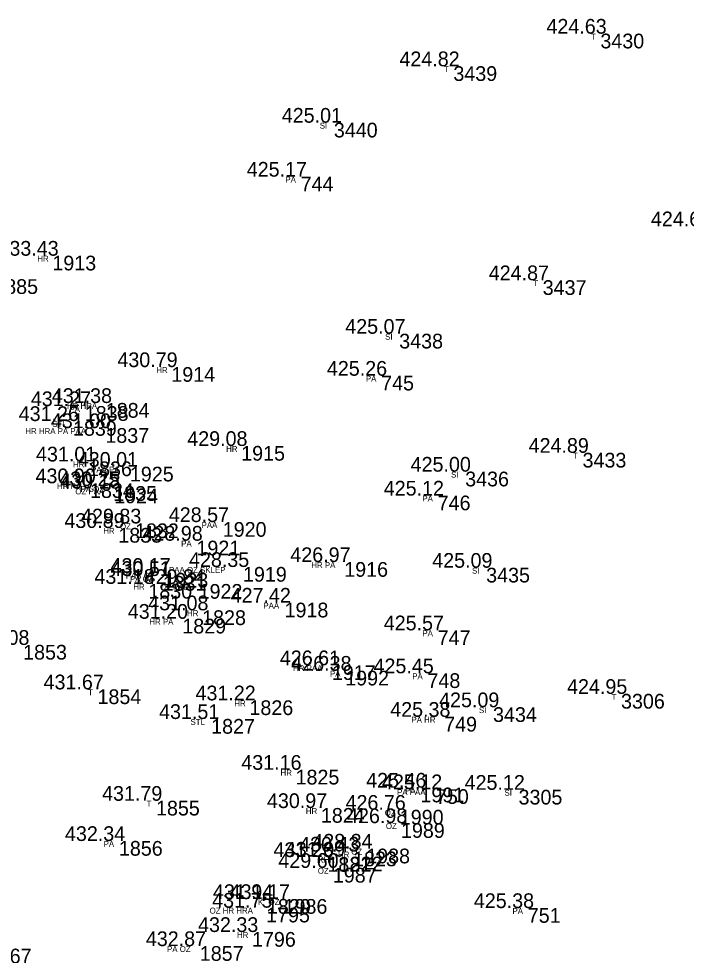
# Model space of a CAD drawing. Extents: x -639390 to -639075, y -1138747 to -1138358.
# Drawn here: x -639298.56 to -639264.56, y -1138517.05 to -1138469.3 of the extents above; entities that cross this region are included whole.
import ezdxf

# ---------------------------------------------------------------- set-up
doc = ezdxf.new("R2010")
doc.units = 0
for name, color, linetype in [('Vrstva 11', 7, 'Continuous'), ('Vrstva 12', 7, 'Continuous'), ('Vrstva 13', 7, 'Continuous'), ('Vrstva 57', 7, 'Continuous')]:
    doc.layers.add(name, color=color, linetype=linetype)

msp = doc.modelspace()

# ---------------------------------------------------------------- linework, layer by layer
at = {"layer": 'Vrstva 11'}
for p, q in [((-639269.21, -1138470.06), (-639269.21, -1138470.06)), ((-639276.7, -1138471.72), (-639276.7, -1138471.72)), ((-639282.79, -1138474.6), (-639282.79, -1138474.6)), ((-639284.48, -1138477.35), (-639284.48, -1138477.35)), ((-639297.13, -1138481.38), (-639297.13, -1138481.38)), ((-639272.15, -1138482.63), (-639272.15, -1138482.63)), ((-639279.46, -1138485.36), (-639279.46, -1138485.36)), ((-639291.07, -1138487.06), (-639291.07, -1138487.06)), ((-639280.38, -1138487.5), (-639280.38, -1138487.5)), ((-639294.41, -1138488.89), (-639294.41, -1138488.89)), ((-639295.48, -1138489.05), (-639295.48, -1138489.05)), ((-639296.08, -1138489.81), (-639296.08, -1138489.81)), ((-639294.43, -1138490.17), (-639294.43, -1138490.17)), ((-639287.51, -1138491.08), (-639287.51, -1138491.08)), ((-639270.12, -1138491.43), (-639270.12, -1138491.43)), ((-639295.31, -1138491.87), (-639295.31, -1138491.87)), ((-639293.18, -1138492.14), (-639293.18, -1138492.14)), ((-639276.1, -1138492.39), (-639276.1, -1138492.39)), ((-639295.21, -1138492.98), (-639295.21, -1138492.98)), ((-639294.03, -1138493.13), (-639294.03, -1138493.13)), ((-639293.98, -1138493.25), (-639293.98, -1138493.25)), ((-639277.5, -1138493.61), (-639277.5, -1138493.61)), ((-639292.92, -1138495.03), (-639292.92, -1138495.03)), ((-639288.45, -1138494.96), (-639288.45, -1138494.96)), ((-639293.77, -1138495.26), (-639293.77, -1138495.26)), ((-639289.79, -1138495.91), (-639289.79, -1138495.91)), ((-639282.26, -1138497), (-639282.26, -1138497)), ((-639287.42, -1138497.25), (-639287.42, -1138497.25)), ((-639275.03, -1138497.29), (-639275.03, -1138497.29)), ((-639291.51, -1138497.71), (-639291.51, -1138497.71)), ((-639291.42, -1138497.55), (-639291.42, -1138497.55)), ((-639292.24, -1138498.11), (-639292.24, -1138498.11)), ((-639289.68, -1138498.12), (-639289.68, -1138498.12)), ((-639285.3, -1138499.07), (-639285.3, -1138499.07)), ((-639290.51, -1138499.89), (-639290.51, -1138499.89)), ((-639289.5, -1138499.46), (-639289.5, -1138499.46)), ((-639277.5, -1138500.48), (-639277.5, -1138500.48)), ((-639282.89, -1138502.26), (-639282.89, -1138502.26)), ((-639282.21, -1138502.54), (-639282.21, -1138502.54)), ((-639278.02, -1138502.67), (-639278.02, -1138502.67)), ((-639294.83, -1138503.49), (-639294.83, -1138503.49)), ((-639268.16, -1138503.72), (-639268.16, -1138503.72)), ((-639287.09, -1138504.05), (-639287.09, -1138504.05)), ((-639274.68, -1138504.4), (-639274.68, -1138504.4)), ((-639289.04, -1138505), (-639289.04, -1138505)), ((-639277.17, -1138504.89), (-639277.17, -1138504.89)), ((-639284.74, -1138507.59), (-639284.74, -1138507.59)), ((-639278.38, -1138508.5), (-639278.38, -1138508.5)), ((-639277.59, -1138508.58), (-639277.59, -1138508.58)), ((-639273.38, -1138508.61), (-639273.38, -1138508.61)), ((-639291.85, -1138509.17), (-639291.85, -1138509.17)), ((-639283.45, -1138509.54), (-639283.45, -1138509.54)), ((-639279.43, -1138509.63), (-639279.43, -1138509.63)), ((-639279.37, -1138510.31), (-639279.37, -1138510.31)), ((-639293.74, -1138511.22), (-639293.74, -1138511.22)), ((-639281.81, -1138511.76), (-639281.81, -1138511.76)), ((-639281.14, -1138511.61), (-639281.14, -1138511.61)), ((-639283.12, -1138512.04), (-639283.12, -1138512.04)), ((-639282.54, -1138512.02), (-639282.54, -1138512.02)), ((-639282.84, -1138512.59), (-639282.84, -1138512.59)), ((-639286.2, -1138514.18), (-639286.2, -1138514.18)), ((-639285.35, -1138514.18), (-639285.35, -1138514.18)), ((-639286.24, -1138514.62), (-639286.24, -1138514.62)), ((-639272.91, -1138514.64), (-639272.91, -1138514.64)), ((-639286.96, -1138515.86), (-639286.96, -1138515.86)), ((-639289.62, -1138516.58), (-639289.62, -1138516.58))]:
    msp.add_line(p, q, dxfattribs=at)

# ---------------------------------------------------------------- texts
at = {"layer": 'Vrstva 12'}
for s, p in [('424.63 ', (-639271.679, -1138470.06)), ('424.82 ', (-639279.169, -1138471.72)), ('425.01 ', (-639285.165, -1138474.6)), ('425.17 ', (-639286.949, -1138477.35)), ('424.62 ', (-639266.359, -1138479.88)), ('433.43 ', (-639299.599, -1138481.38)), ('424.87 ', (-639274.619, -1138482.63)), ('425.07 ', (-639281.929, -1138485.36)), ('430.79 ', (-639293.539, -1138487.06)), ('425.26 ', (-639282.866, -1138487.5)), ('431.27 ', (-639297.949, -1138489.05)), ('431.38 ', (-639296.879, -1138488.89)), ('431.26 ', (-639298.566, -1138489.81)), ('431.00 ', (-639296.929, -1138490.17)), ('429.08 ', (-639289.979, -1138491.08)), ('424.89 ', (-639272.589, -1138491.43)), ('431.01 ', (-639297.685, -1138491.87)), ('430.01 ', (-639295.555, -1138492.14)), ('425.00 ', (-639278.599, -1138492.39)), ('430.90 ', (-639297.709, -1138492.98)), ('430.25 ', (-639296.5, -1138493.13)), ('430.18 ', (-639296.449, -1138493.25)), ('425.12 ', (-639279.969, -1138493.61)), ('428.57 ', (-639290.919, -1138494.96)), ('430.89 ', (-639296.239, -1138495.26)), ('429.83 ', (-639295.389, -1138495.03)), ('428.98 ', (-639292.259, -1138495.91)), ('428.35 ', (-639289.89, -1138497.25)), ('426.97 ', (-639284.729, -1138497)), ('425.09 ', (-639277.499, -1138497.29)), ('430.17 ', (-639293.889, -1138497.55)), ('430.51 ', (-639293.885, -1138497.71)), ('431.18 ', (-639294.709, -1138498.11)), ('429.84 ', (-639292.149, -1138498.12)), ('427.42 ', (-639287.769, -1138499.07)), ('431.08 ', (-639291.969, -1138499.46)), ('431.20 ', (-639293.009, -1138499.89)), ('425.57 ', (-639279.969, -1138500.48)), ('432.08 ', (-639301.089, -1138501.22)), ('426.61 ', (-639285.265, -1138502.26)), ('426.38 ', (-639284.679, -1138502.54)), ('425.45 ', (-639280.49, -1138502.67)), ('431.67 ', (-639297.299, -1138503.49)), ('424.95 ', (-639270.63, -1138503.72)), ('431.22 ', (-639289.559, -1138504.05)), ('425.09 ', (-639277.149, -1138504.4)), ('425.38 ', (-639279.639, -1138504.89)), ('431.51 ', (-639291.415, -1138505)), ('431.16 ', (-639287.226, -1138507.59)), ('425.46 ', (-639280.866, -1138508.5)), ('425.12 ', (-639280.059, -1138508.58)), ('425.12 ', (-639275.849, -1138508.61)), ('431.79 ', (-639294.319, -1138509.17)), ('430.97 ', (-639285.919, -1138509.54)), ('426.76 ', (-639281.916, -1138509.63)), ('426.98 ', (-639281.839, -1138510.31)), ('432.34 ', (-639296.209, -1138511.22)), ('428.84 ', (-639283.609, -1138511.61)), ('431.23 ', (-639285.589, -1138512.04)), ('431.09 ', (-639285.009, -1138512.02)), ('430.43 ', (-639284.279, -1138511.76)), ('429.60 ', (-639285.339, -1138512.59)), ('431.94 ', (-639288.669, -1138514.18)), ('431.17 ', (-639287.819, -1138514.18)), ('431.75 ', (-639288.71, -1138514.62)), ('425.38 ', (-639275.379, -1138514.64)), ('432.33 ', (-639289.429, -1138515.86)), ('432.87 ', (-639292.089, -1138516.58))]:
    msp.add_text(s, height=0.75, dxfattribs=at).set_placement(p)
at = {"layer": 'Vrstva 13'}
for s, p in [(' 3430', (-639269.21, -1138470.81)), (' 3439', (-639276.7, -1138472.47)), (' 3440', (-639282.79, -1138475.35)), (' 744', (-639284.48, -1138478.1)), (' 1913', (-639297.13, -1138482.13)), (' 1885', (-639300.09, -1138483.33)), (' 3437', (-639272.15, -1138483.38)), (' 3438', (-639279.46, -1138486.11)), (' 1914', (-639291.07, -1138487.81)), (' 745', (-639280.38, -1138488.25)), (' 1884', (-639294.41, -1138489.64)), (' 1838', (-639295.48, -1138489.8)), (' 1839', (-639296.08, -1138490.56)), (' 1837', (-639294.43, -1138490.92)), (' 1915', (-639287.51, -1138491.83)), (' 3433', (-639270.12, -1138492.18)), (' 1836', (-639295.31, -1138492.62)), (' 1925', (-639293.18, -1138492.89)), (' 3436', (-639276.1, -1138493.14)), (' 1834', (-639295.21, -1138493.73)), (' 1835', (-639294.03, -1138493.88)), (' 1924', (-639293.98, -1138494)), (' 746', (-639277.5, -1138494.36)), (' 1832', (-639292.92, -1138495.78)), (' 1920', (-639288.45, -1138495.71)), (' 1833', (-639293.77, -1138496.01)), (' 1921', (-639289.79, -1138496.66)), (' 1916', (-639282.26, -1138497.75)), (' 1923', (-639291.42, -1138498.3)), (' 1919', (-639287.42, -1138498)), (' 3435', (-639275.03, -1138498.04)), (' 1831', (-639291.51, -1138498.46)), (' 1830', (-639292.24, -1138498.86)), (' 1922', (-639289.68, -1138498.87)), (' 1828', (-639289.5, -1138500.21)), (' 1918', (-639285.3, -1138499.82)), (' 1829', (-639290.51, -1138500.64)), (' 747', (-639277.5, -1138501.23)), (' 1853', (-639298.62, -1138501.97)), (' 1917', (-639282.89, -1138503.01)), (' 1992', (-639282.21, -1138503.29)), (' 748', (-639278.02, -1138503.42)), (' 1854', (-639294.83, -1138504.24)), (' 3306', (-639268.16, -1138504.47)), (' 1826', (-639287.09, -1138504.8)), (' 3434', (-639274.68, -1138505.15)), (' 1827', (-639289.04, -1138505.75)), (' 749', (-639277.17, -1138505.64)), (' 1825', (-639284.74, -1138508.34)), (' 1991', (-639278.38, -1138509.25)), (' 750', (-639277.59, -1138509.33)), (' 3305', (-639273.38, -1138509.36)), (' 1855', (-639291.85, -1138509.92)), (' 1824', (-639283.45, -1138510.29)), (' 1990', (-639279.43, -1138510.38)), (' 1989', (-639279.37, -1138511.06)), (' 1856', (-639293.74, -1138511.97)), (' 1823', (-639281.81, -1138512.51)), (' 1988', (-639281.14, -1138512.36)), (' 1821', (-639283.12, -1138512.79)), (' 1822', (-639282.54, -1138512.77)), (' 1987', (-639282.84, -1138513.34)), (' 1820', (-639286.2, -1138514.93)), (' 1986', (-639285.35, -1138514.93)), (' 1795', (-639286.24, -1138515.37)), (' 751', (-639272.91, -1138515.39)), (' 1796', (-639286.96, -1138516.61)), (' 1857', (-639289.62, -1138517.33)), (' 1867', (-639300.42, -1138517.46))]:
    msp.add_text(s, height=0.75, dxfattribs=at).set_placement(p)
at = {"layer": 'Vrstva 57'}
for s, p in [('T', (-639269.41, -1138470.36)), ('T', (-639276.9, -1138472.02)), ('SI', (-639283.228, -1138474.9)), ('PA', (-639284.98, -1138477.65)), ('HR', (-639297.619, -1138481.68)), ('T', (-639272.35, -1138482.93)), ('SI', (-639279.898, -1138485.66)), ('HR', (-639291.559, -1138487.36)), ('PA', (-639280.88, -1138487.8)), ('HR HRA', (-639296.11, -1138489.19)), ('PA', (-639295.98, -1138489.35)), ('STL', (-639296.855, -1138490.11)), ('HR HRA PA PAA', (-639298.23, -1138490.47)), ('HR', (-639287.999, -1138491.38)), ('T', (-639270.32, -1138491.73)), ('HR', (-639295.799, -1138492.17)), ('PAA PA', (-639294.88, -1138492.44)), ('SI', (-639276.538, -1138492.69)), ('HR PA', (-639296.61, -1138493.28)), ('OZ PAA', (-639295.68, -1138493.55)), ('PA OZ', (-639295.419, -1138493.43)), ('PA', (-639278, -1138493.91)), ('OZ', (-639293.409, -1138495.33)), ('PAA', (-639289.25, -1138495.26)), ('HR', (-639294.259, -1138495.56)), ('PA', (-639290.29, -1138496.21)), ('HR PA', (-639283.66, -1138497.3)), ('PAB OZ', (-639293.109, -1138497.85)), ('PAA OZ SKLEP', (-639290.909, -1138497.55)), ('SI', (-639275.468, -1138497.59)), ('PA OZ', (-639292.899, -1138498.01)), ('HR', (-639292.729, -1138498.41)), ('OZ PAB', (-639291.369, -1138498.42)), ('PAA', (-639286.1, -1138499.37)), ('HR PA', (-639291.91, -1138500.19)), ('HR', (-639289.989, -1138499.76)), ('PA', (-639278, -1138500.78)), ('HR PAA', (-639284.59, -1138502.56)), ('PA', (-639282.71, -1138502.84)), ('PA', (-639278.52, -1138502.97)), ('T', (-639295.03, -1138503.79)), ('T', (-639268.36, -1138504.02)), ('HR', (-639287.579, -1138504.35)), ('SI', (-639275.118, -1138504.7)), ('STL', (-639289.815, -1138505.3)), ('PA HR', (-639278.559, -1138505.19)), ('HR', (-639285.229, -1138507.89)), ('PA', (-639278.88, -1138508.8)), ('PA PAA', (-639279.29, -1138508.88)), ('SI', (-639273.818, -1138508.91)), ('T', (-639292.05, -1138509.47)), ('HR', (-639283.939, -1138509.84)), ('OZ', (-639279.919, -1138509.93)), ('OZ', (-639279.859, -1138510.61)), ('PA', (-639294.24, -1138511.52)), ('HR', (-639282.299, -1138512.06)), ('OZ', (-639281.629, -1138511.91)), ('K', (-639283.295, -1138512.34)), ('HR', (-639283.029, -1138512.32)), ('OZ', (-639283.329, -1138512.89)), ('K', (-639286.375, -1138514.48)), ('OZ', (-639285.839, -1138514.48)), ('OZ HR HRA', (-639288.84, -1138514.92)), ('PA', (-639273.41, -1138514.94)), ('HR', (-639287.449, -1138516.16)), ('PA OZ', (-639291.009, -1138516.88))]:
    msp.add_text(s, height=0.3, dxfattribs=at).set_placement(p)

doc.saveas('drawing.dxf')
